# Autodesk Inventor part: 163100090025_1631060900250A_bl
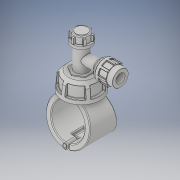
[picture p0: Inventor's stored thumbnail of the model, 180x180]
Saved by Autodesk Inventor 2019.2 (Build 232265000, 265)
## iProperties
Created: 2022-02
Part Number: 163100090025_1631060900250A_bl
Material: Generic
Description: Plassadle Tapper 90x25
Document SubType Name: Modeling
Designer: comp2
Density: 1 g/cm^3
Appearance: Default
Author: comp2
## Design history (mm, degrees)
derived "16310.ipt"
feature "Solid1::16310.ipt" dims "ScaleForDerivedMember" = 10
feature "Solid2::16310.ipt" dims "ScaleForDerivedMember" = 10
feature "Solid3::16310.ipt" dims "ScaleForDerivedMember" = 10
feature "Solid4::16310.ipt" dims "ScaleForDerivedMember" = 10
tag "TaggingFeature1"
body "Solid1"
body "Solid2"
body "Solid3"
body "Solid4"
other parameters: "d2" = 119 [user parameter], "d3" = 45 [user parameter], "d5" = 258 [user parameter], "d7" = 113.05 [user parameter], "d8" = 85 deg [user parameter], "d9" = 45 deg [user parameter], "d10" = 102 [user parameter], "d11" = 49 [user parameter], "d12" = 34.3 [user parameter], "d13" = 35.7 [user parameter], "d14" = 55.08 [user parameter], "d15" = 2.45 [user parameter], "d16" = 2 [user parameter], "d17" = 2 [user parameter], "d18" = 29.4 [user parameter], "d19" = 7.35 [user parameter], "d20" = 1 [user parameter], "d21" = 30.6 [user parameter], "d22" = 1 [user parameter], "d23" = 14.7 [user parameter], "d24" = 106 [user parameter], "d27" = 144 [user parameter], "d29" = 54 [user parameter], "d31" = 43.2 [user parameter], "d32" = 42.4 [user parameter], "d33" = 14.84 [user parameter], "d34" = 93 deg [user parameter], "d35" = 2 [user parameter], "d36" = 4 [user parameter], "d39" = 45 deg [user parameter], "d40" = 4 [user parameter], "d41" = 5 [user parameter], "d42" = 2.9 [user parameter], "d46" = 51 [user parameter], "d47" = 27 [user parameter], "d48" = 49 [user parameter], "d49" = 2.38 [user parameter], "d50" = 94 [user parameter], "d51" = 0 [user parameter], "d52" = 20.3 [user parameter], "d53" = 65.45 [user parameter], "d54" = 32.9 [user parameter], "d55" = 0 [user parameter], "d56" = 18.8 [user parameter], "d57" = 18.8 [user parameter], "d59" = 0 [user parameter], "d60" = 94 [user parameter], "d61" = 0 [user parameter], "d62" = 32.9 [user parameter], "d63" = 0 [user parameter], "d65" = 0 [user parameter], "d67" = 0 [user parameter], "d69" = 0 [user parameter], "d70" = 1 [user parameter], "d71" = 90.24 [user parameter], "d72" = 0 [user parameter], "d73" = 2 [user parameter], "d77" = 25 [user parameter], "d78" = 86.7 [user parameter], "d79" = 5.1 [user parameter], "d80" = 60 deg [user parameter], "d81" = 5.1 [user parameter], "d84" = 0 [user parameter], "d85" = 1 [user parameter], "d87" = 360 deg [user parameter], "d90" = 0 [user parameter], "d91" = 1 [user parameter], "d93" = 60 deg [user parameter], "d94" = 3.06 [user parameter], "d95" = 3.06 [user parameter], "d97" = 0 [user parameter], "d98" = 0.5 [user parameter], "d100" = 360 deg [user parameter], "d102" = 2 [user parameter], "d105" = 0 [user parameter], "d106" = 45 deg [user parameter], "d107" = 2.7 [user parameter], "d108" = 2.7 [user parameter], "d109" = 2.95332 [user parameter], "d110" = -8 [user parameter], "d112" = 0 [user parameter], "d113" = 0.5 [user parameter], "d115" = 360 deg [user parameter], "d117" = 0.5 [user parameter], "d1" = 25 [user parameter], "B" = 119 [user parameter], "L" = 94 [user parameter], "E_" = 54 [user parameter], "E1" = 102 [user parameter], "H1" = 258 [user parameter], "H2" = 144 [user parameter], "H3" = 106 [user parameter], "H_costum" = 49 [user parameter]
